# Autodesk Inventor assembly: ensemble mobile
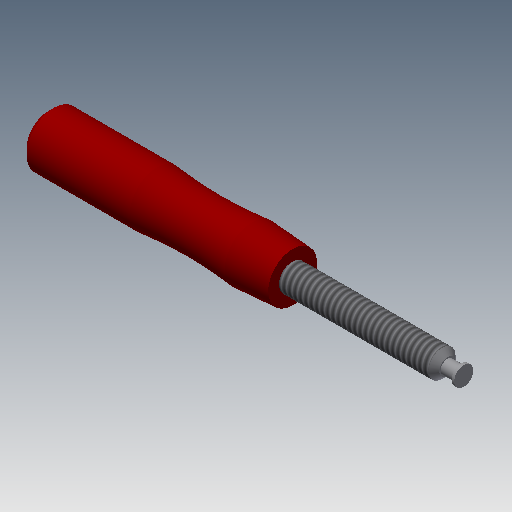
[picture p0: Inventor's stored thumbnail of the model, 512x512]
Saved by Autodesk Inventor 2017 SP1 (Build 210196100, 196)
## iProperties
Created: 2015-12
Part Number: ensemble mobile
Material: Générique
Document SubType Name: Assembly
Designer: Papa
Mass: 30.7735 g
Surface Area: 86.4284 cm^2
Volume: 30.7735 cm^3
Density: 1 g/cm^3
Author: Papa
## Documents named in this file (3)
- H:\Consmec\1si\Cours\Leçon 04 - Schématisation\04-02-TD Schematisation\04-02-04-TD4Serre Joint\04-02-04-02-SerreJoint 3D\ensemble mobile.iam
- H:\Consmec\1si\Cours\Leçon 04 - Schématisation\04-02-TD Schematisation\04-02-04-TD4Serre Joint\04-02-04-02-SerreJoint 3D\07-Poignet.ipt
- H:\Consmec\1si\Cours\Leçon 04 - Schématisation\04-02-TD Schematisation\04-02-04-TD4Serre Joint\04-02-04-02-SerreJoint 3D\06-Vis TR10.ipt
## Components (2 placed, 2 different names)
1. 07-Poignet:1 — Logement:1, Angle:1
2. 06-Vis TR10:1 — Logement:1, Angle:1
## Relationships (2: Insert 1, Angle 1)
- Logement:1 [Insert]: 07-Poignet:1 ↔ 06-Vis TR10:1
- Angle:1: 07-Poignet:1 ↔ 06-Vis TR10:1
